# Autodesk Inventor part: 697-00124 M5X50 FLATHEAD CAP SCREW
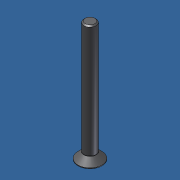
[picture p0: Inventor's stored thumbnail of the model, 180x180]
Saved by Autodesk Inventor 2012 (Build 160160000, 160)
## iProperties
Created: 2013-10
Part Number: 697-00124 M5X50 FLATHEAD CAP SCREW
Material: Default
Document SubType Name: Modeling
Designer: Admin
Density: 1 g/cm^3
Author: Admin
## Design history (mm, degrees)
node "697-00124 M5X50 FLATHEAD CAP SCREW1"
node "Base1"
body "Solid1"
